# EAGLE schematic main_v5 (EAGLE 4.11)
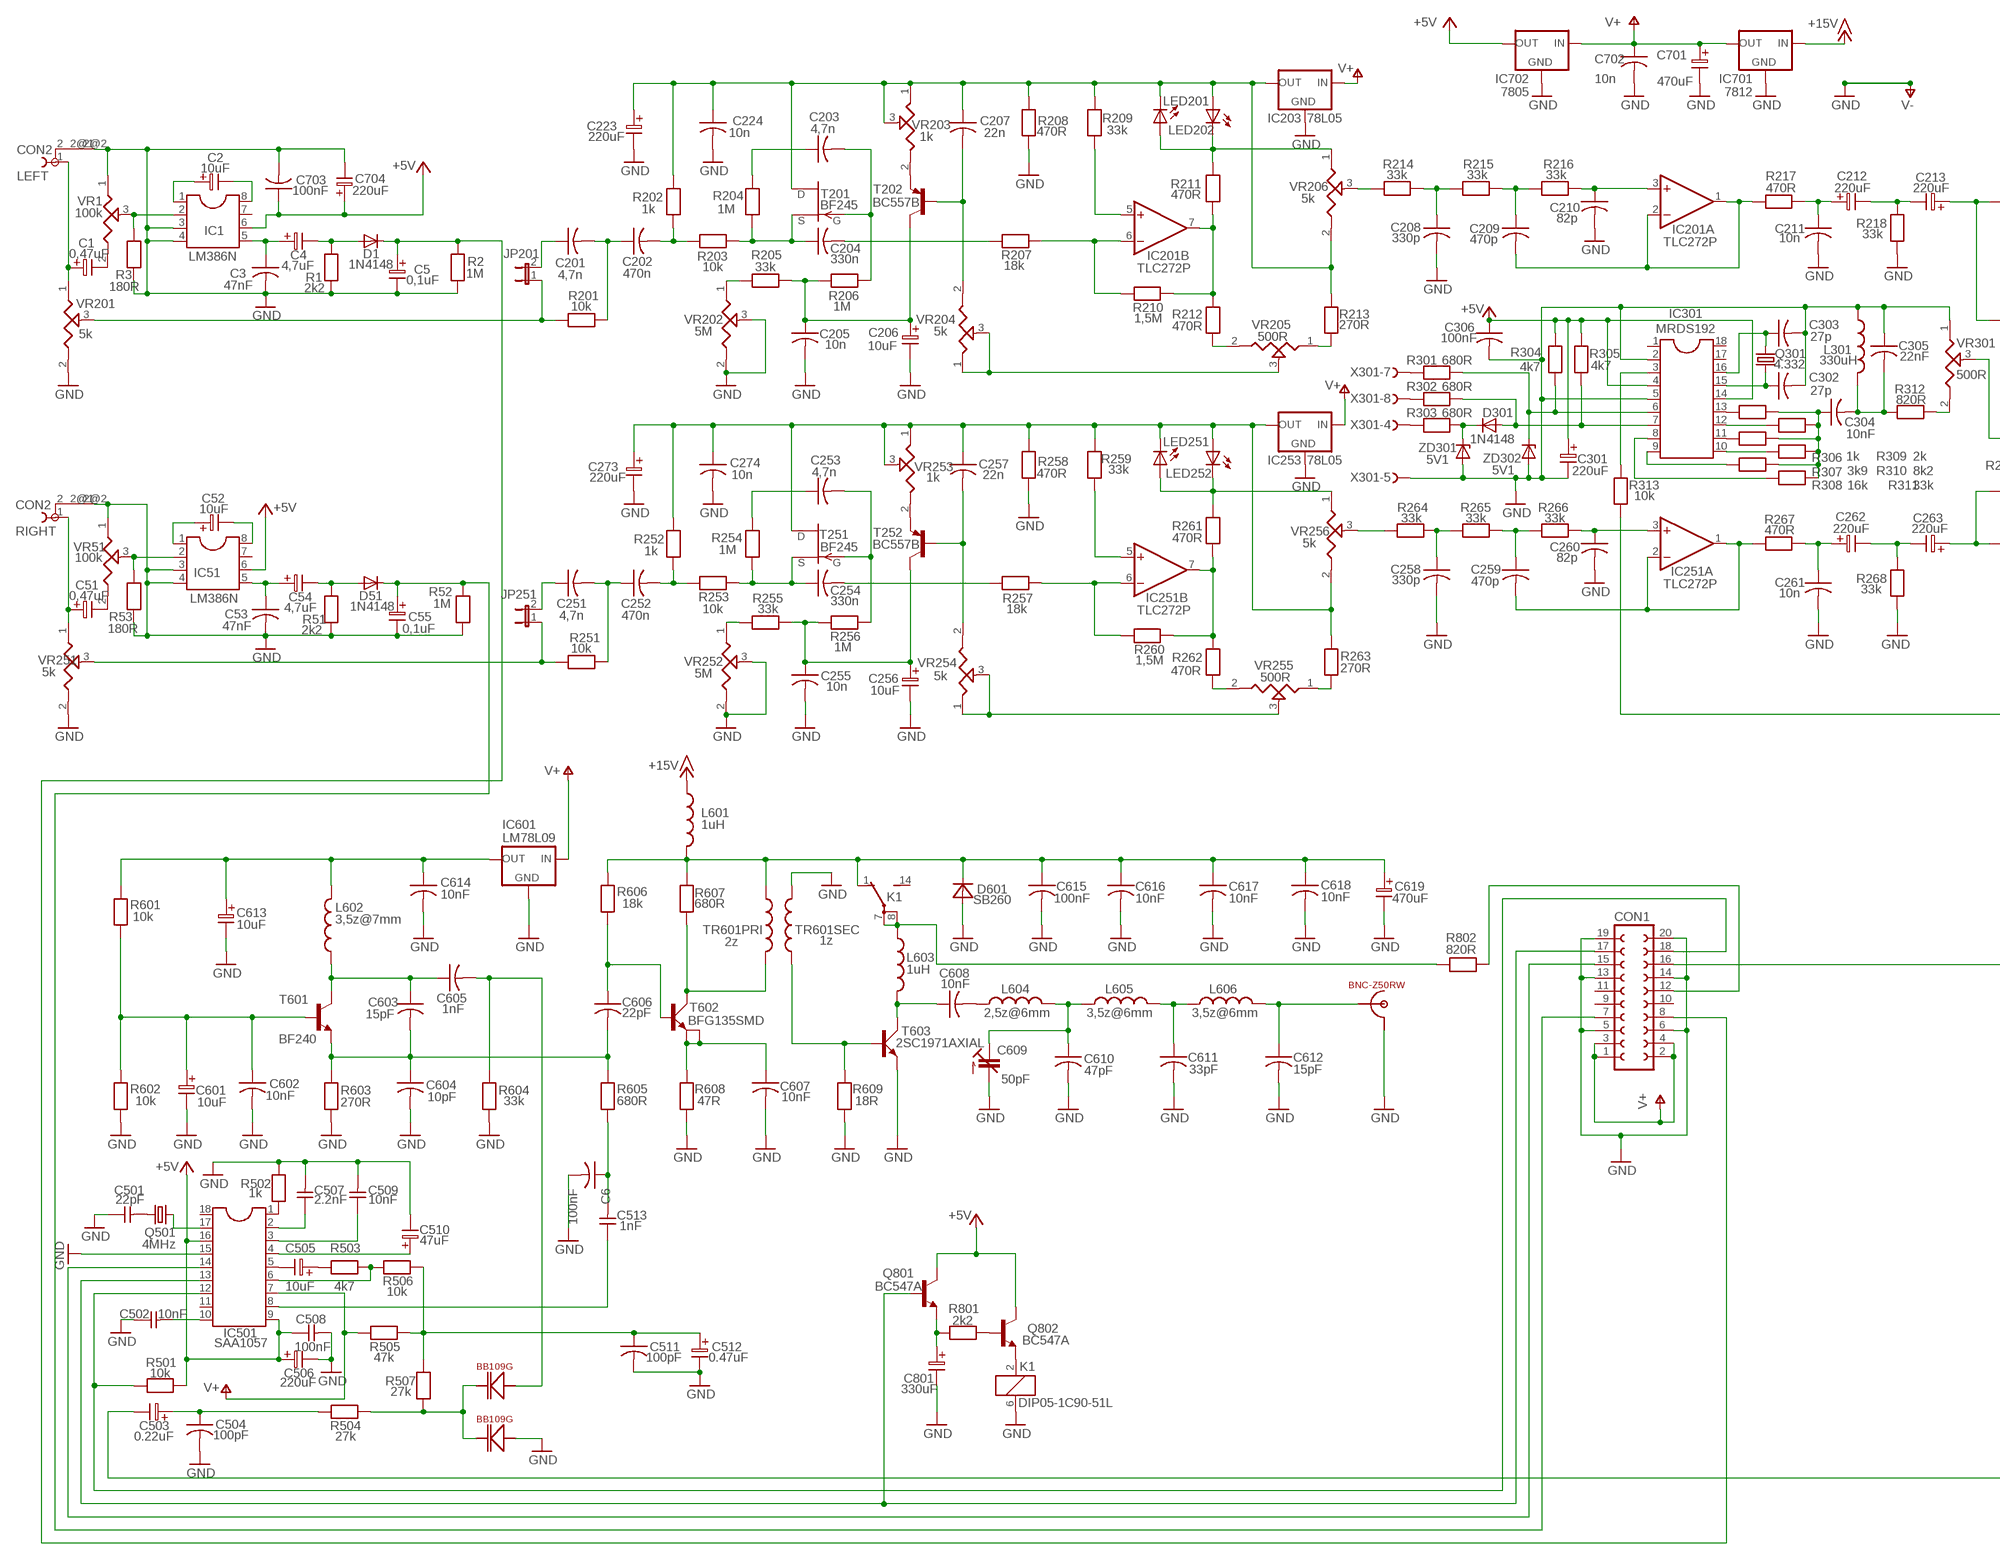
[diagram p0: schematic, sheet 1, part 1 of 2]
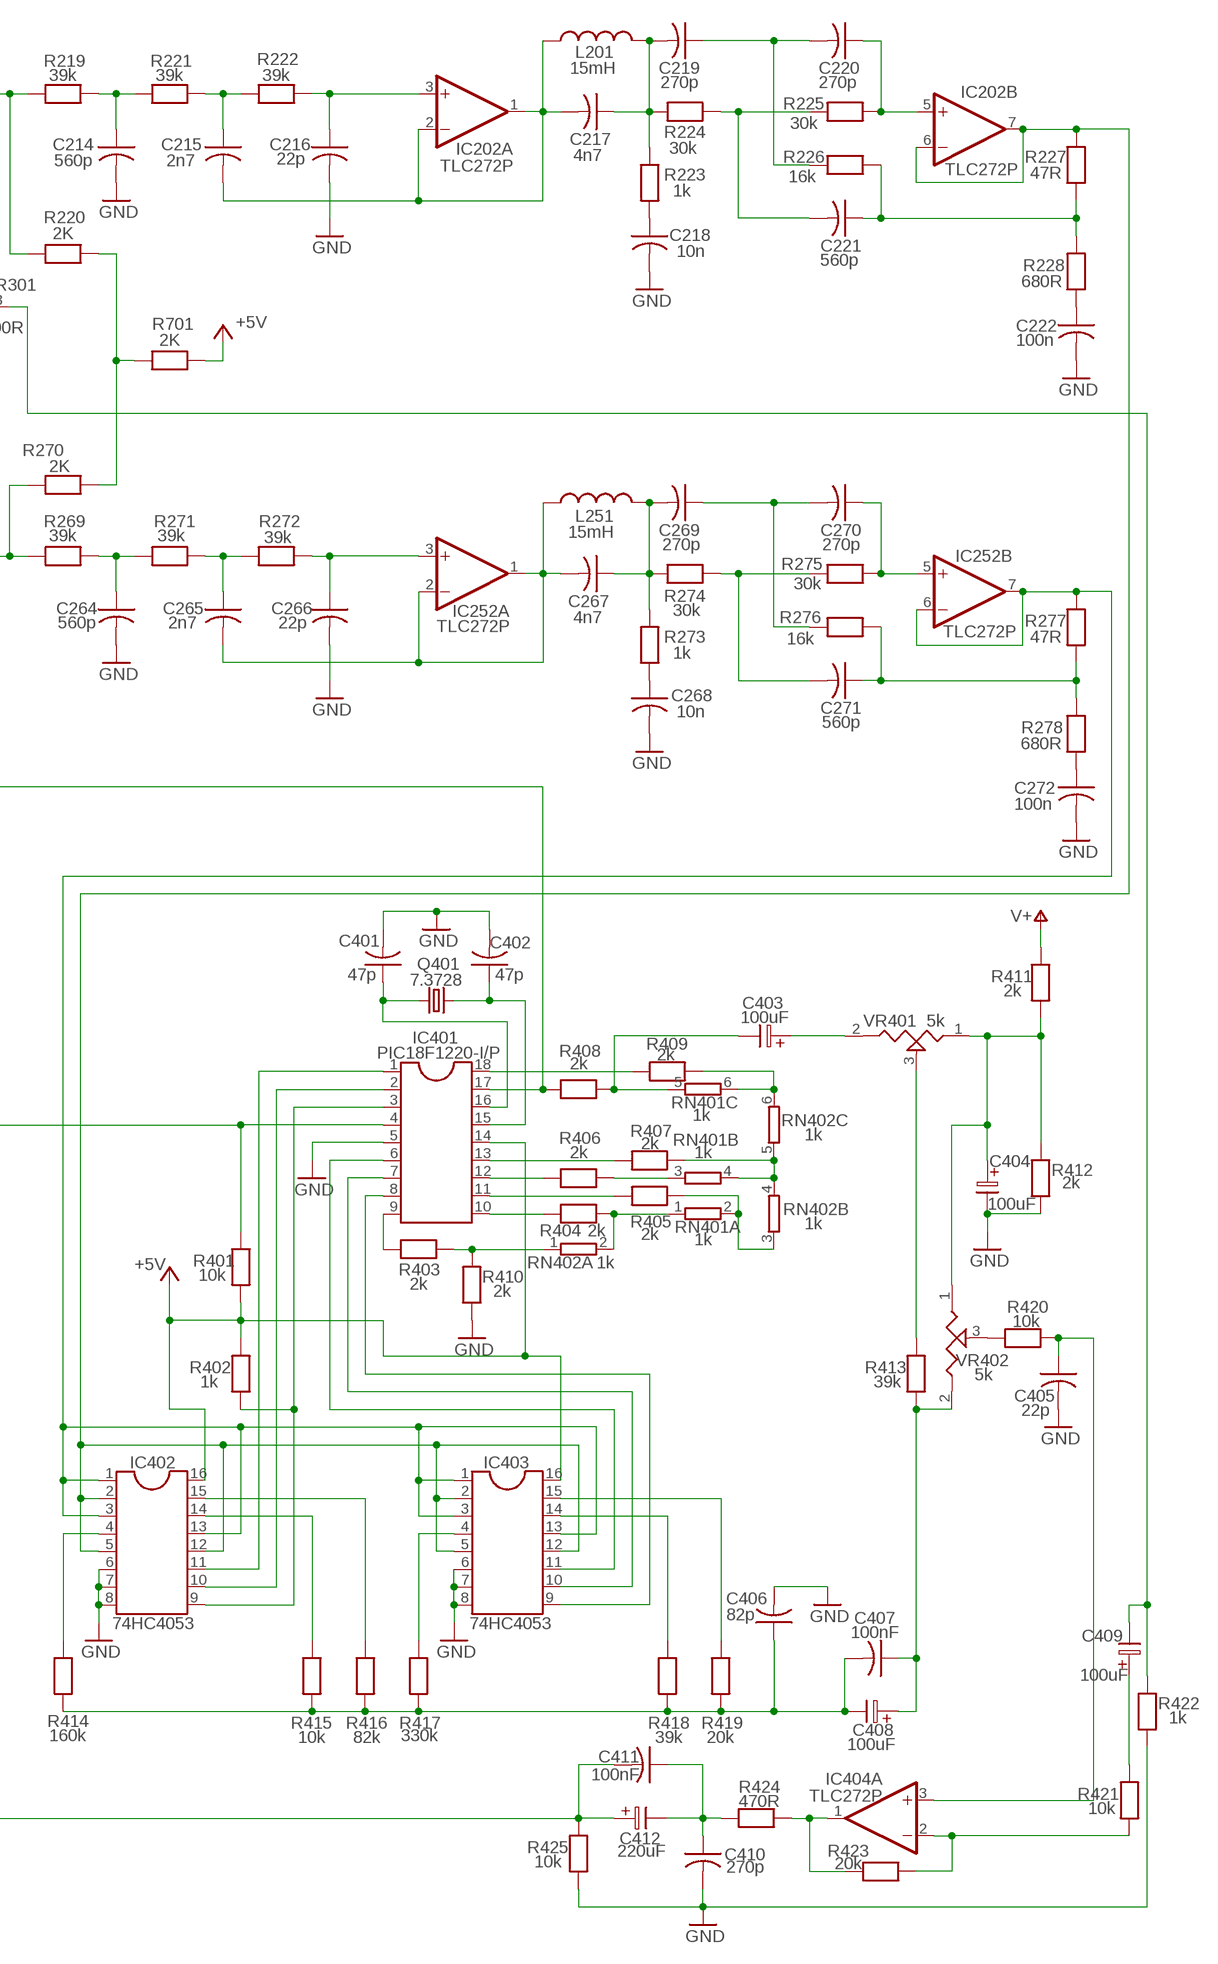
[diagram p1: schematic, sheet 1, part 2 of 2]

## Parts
C1  0,47uF  ELC-2,5  [ES-2,5]
C2  10uF  ELC-2,5  [ES-2,5]
C3  47nF  CAP-5  [C-5]
C4  4,7uF  ELC-2,5  [ES-2,5]
C5  0,1uF  ELC-2,5  [ES-2,5]
C6  100nF  CAP-5  [C-5]
C51  0,47uF  ELC-2,5  [ES-2,5]
C52  10uF  ELC-2,5  [ES-2,5]
C53  47nF  CAP-5  [C-5]
C54  4,7uF  ELC-2,5  [ES-2,5]
C55  0,1uF  ELC-2,5  [ES-2,5]
C201  4,7n  CAP-5  [C-5]
C202  470n  CAP-5  [C-5]
C203  4,7n  CAP-5  [C-5]
C204  330n  CAP-5  [C-5]
C205  10n  CAP-5  [C-5]
C206  10uF  ELC-2,5  [ES-2,5]
C207  22n  CAP-5  [C-5]
C208  330p  CAP-5  [C-5]
C209  470p  CAP-5  [C-5]
C210  82p  CAP-5  [C-5]
C211  10n  CAP-5  [C-5]
C212  220uF  ELC-5  [ES-5]
C213  220uF  ELC-2,5  [ES-2,5]
C214  560p  CAP-5  [C-5]
C215  2n7  CAP-5  [C-5]
C216  22p  CAP-5  [C-5]
C217  4n7  CAP-5  [C-5]
C218  10n  CAP-5  [C-5]
C219  270p  CAP-5  [C-5]
C220  270p  CAP-5  [C-5]
C221  560p  CAP-5  [C-5]
C222  100n  CAP-5  [C-5]
C223  220uF  ELC-2,5  [ES-2,5]
C224  10n  CAP-5  [C-5]
C251  4,7n  CAP-5  [C-5]
C252  470n  CAP-5  [C-5]
C253  4,7n  CAP-5  [C-5]
C254  330n  CAP-5  [C-5]
C255  10n  CAP-5  [C-5]
C256  10uF  ELC-2,5  [ES-2,5]
C257  22n  CAP-5  [C-5]
C258  330p  CAP-5  [C-5]
C259  470p  CAP-5  [C-5]
C260  82p  CAP-5  [C-5]
C261  10n  CAP-5  [C-5]
C262  220uF  ELC-5  [ES-5]
C263  220uF  ELC-2,5  [ES-2,5]
C264  560p  CAP-5  [C-5]
C265  2n7  CAP-5  [C-5]
C266  22p  CAP-5  [C-5]
C267  4n7  CAP-5  [C-5]
C268  10n  CAP-5  [C-5]
C269  270p  CAP-5  [C-5]
C270  270p  CAP-5  [C-5]
C271  560p  CAP-5  [C-5]
C272  100n  CAP-5  [C-5]
C273  220uF  ELC-2,5  [ES-2,5]
C274  10n  CAP-5  [C-5]
C301  220uF  ELC-5  [ES-5]
C302  27p  CAP-5  [C-5]
C303  27p  CAP-5  [C-5]
C304  10nF  CAP-5  [C-5]
C305  22nF  CAP-5  [C-5]
C306  100nF  CAP-5  [C-5]
C401  47p  CAP-5  [C-5]
C402  47p  CAP-5  [C-5]
C403  100uF  ELC-5  [ES-5]
C404  100uF  ELC-5  [ES-5]
C405  22p  CAP-5  [C-5]
C406  82p  CAP-5  [C-5]
C407  100nF  CAP-5  [C-5]
C408  100uF  ELC-5  [ES-5]
C409  100uF  ELC-5  [ES-5]
C410  270p  CAP-5  [C-5]
C411  100nF  CAP-5  [C-5]
C412  220uF  ELC-5  [ES-5]
C501  22pF  CAPNP-5  [C-5]
C502  10nF  CAPNP-5  [C-5]
C503  0.22uF  ELC-2,5  [ES-2,5]
C504  100pF  CAP-5  [C-5]
C505  10uF  ELC-2,5  [ES-2,5]
C506  220uF  ELC-5  [ES-5]
C507  2.2nF  CAPNP-5  [C-5]
C508  100nF  CAPNP-5  [C-5]
C509  10nF  CAPNP-5  [C-5]
C510  47uF  ELC-2,5  [ES-2,5]
C511  100pF  CAP-5  [C-5]
C512  0.47uF  ELC-2,5  [ES-2,5]
C513  1nF  CAPNP-5  [C-5]
C601  10uF  ELC-2,5  [ES-2,5]
C602  10nF  CAP-5  [C-5]
C603  15pF  CAP-5  [C-5]
C604  10pF  CAP-5  [C-5]
C605  1nF  CAP-5  [C-5]
C606  22pF  CAP-5  [C-5]
C607  10nF  CAP-5  [C-5]
C608  10nF  CAP-5  [C-5]
C609  50pF  C-TRIMM3008  [3008]
C610  47pF  CAP-5  [C-5]
C611  33pF  CAP-5  [C-5]
C612  15pF  CAP-5  [C-5]
C613  10uF  ELC-2,5  [ES-2,5]
C614  10nF  CAP-5  [C-5]
C615  100nF  CAP-5  [C-5]
C616  10nF  CAP-5  [C-5]
C617  10nF  CAP-5  [C-5]
C618  10nF  CAP-5  [C-5]
C619  470uF  ELC-5L  [ES-5L]
C701  470uF  ELC-5L  [ES-5L]
C702  10n  CAP-5  [C-5]
C703  100nF  CAP-5  [C-5]
C704  220uF  ELC-5  [ES-5]
C801  330uF  ELC-5  [ES-5]
CON1  FE10-2  [FE10-2]
D1  1N4148  [DO35-10]
D51  1N4148  [DO35-10]
D301  1N4148  [DO35-10]
D601  SB260  DIODE-7,5  [D-7,5]
IC1  LM386N  DIL8  [DIL08]
IC51  LM386N  DIL8  [DIL08]
IC201  TLC272P  [DIL08]
IC202  TLC272P  [DIL08]
IC203  78L05  78LXX  [78LXX]
IC251  TLC272P  [DIL08]
IC252  TLC272P  [DIL08]
IC253  78L05  78LXX  [78LXX]
IC301  MRDS192  DIL18  [DIL18]
IC401  PIC18F1220-I/P  DIL18  [DIL18]
IC402  74HC4053  DIL16  [DIL16]
IC403  74HC4053  DIL16  [DIL16]
IC404  TLC272P  [DIL08]
IC501  SAA1057  DIL18S  [SOCKED-18]
IC601  LM78L09  78LXX  [78LXX]
IC701  7812  78XXL  [78XXL]
IC702  7805  78XXL  [78XXL]
JP201  JP1E  [JP1]
JP251  JP1E  [JP1]
K1  DIP05-1C90-51L  RR1U  [RR1U]
L201  15mH  L-5  [L-5]
L251  15mH  L-5  [L-5]
L301  330uH  L-5  [L-5]
L601  1uH  L-12,5  [L-12,5]
L602  3,5z@7mm  L-10  [L-10]
L603  1uH  L-12,5  [L-12,5]
L604  2,5z@6mm  L-7,5  [L-7,5]
L605  3,5z@6mm  L-10  [L-10]
L606  3,5z@6mm  L-10  [L-10]
LED201  LED5MM  [LED5MM]
LED202  LED5MM  [LED5MM]
LED251  LED5MM  [LED5MM]
LED252  LED5MM  [LED5MM]
LEFT  CON2  TOBU3  [TOBU3]
Q301  4.332  CRYTALHC49S  [HC49/S]
Q401  7.3728  CRYTALHC49U-V  [HC49U-V]
Q501  4MHz  CRYTALHC49U-V  [HC49U-V]
Q801  BC547A  [TO92]
Q802  BC547A  [TO92]
R1  2k2  RESEU-7,5  [R-7,5]
R2  1M  RESEU-7,5  [R-7,5]
R3  180R  RESEU-7,5  [R-7,5]
R51  2k2  RESEU-7,5  [R-7,5]
R52  1M  RESEU-7,5  [R-7,5]
R53  180R  RESEU-7,5  [R-7,5]
R201  10k  RESEU-7,5  [R-7,5]
R202  1k  RESEU-7,5  [R-7,5]
R203  10k  RESEU-7,5  [R-7,5]
R204  1M  RESEU-7,5  [R-7,5]
R205  33k  RESEU-7,5  [R-7,5]
R206  1M  RESEU-7,5  [R-7,5]
R207  18k  RESEU-7,5  [R-7,5]
R208  470R  RESEU-7,5  [R-7,5]
R209  33k  RESEU-7,5  [R-7,5]
R210  1,5M  RESEU-7,5  [R-7,5]
R211  470R  RESEU-7,5  [R-7,5]
R212  470R  RESEU-7,5  [R-7,5]
R213  270R  RESEU-7,5  [R-7,5]
R214  33k  RESEU-7,5  [R-7,5]
R215  33k  RESEU-7,5  [R-7,5]
R216  33k  RESEU-7,5  [R-7,5]
R217  470R  RESEU-7,5  [R-7,5]
R218  33k  RESEU-7,5  [R-7,5]
R219  39k  RESEU-7,5  [R-7,5]
R220  2K  RESEU-7,5  [R-7,5]
R221  39k  RESEU-7,5  [R-7,5]
R222  39k  RESEU-7,5  [R-7,5]
R223  1k  RESEU-7,5  [R-7,5]
R224  30k  RESEU-7,5  [R-7,5]
R225  30k  RESEU-7,5  [R-7,5]
R226  16k  RESEU-7,5  [R-7,5]
R227  47R  RESEU-7,5  [R-7,5]
R228  680R  RESEU-7,5  [R-7,5]
R251  10k  RESEU-7,5  [R-7,5]
R252  1k  RESEU-7,5  [R-7,5]
R253  10k  RESEU-7,5  [R-7,5]
R254  1M  RESEU-7,5  [R-7,5]
R255  33k  RESEU-7,5  [R-7,5]
R256  1M  RESEU-7,5  [R-7,5]
R257  18k  RESEU-7,5  [R-7,5]
R258  470R  RESEU-7,5  [R-7,5]
R259  33k  RESEU-7,5  [R-7,5]
R260  1,5M  RESEU-7,5  [R-7,5]
R261  470R  RESEU-7,5  [R-7,5]
R262  470R  RESEU-7,5  [R-7,5]
R263  270R  RESEU-7,5  [R-7,5]
R264  33k  RESEU-7,5  [R-7,5]
R265  33k  RESEU-7,5  [R-7,5]
R266  33k  RESEU-7,5  [R-7,5]
R267  470R  RESEU-7,5  [R-7,5]
R268  33k  RESEU-7,5  [R-7,5]
R269  39k  RESEU-7,5  [R-7,5]
R270  2K  RESEU-7,5  [R-7,5]
R271  39k  RESEU-7,5  [R-7,5]
R272  39k  RESEU-7,5  [R-7,5]
R273  1k  RESEU-7,5  [R-7,5]
R274  30k  RESEU-7,5  [R-7,5]
R275  30k  RESEU-7,5  [R-7,5]
R276  16k  RESEU-7,5  [R-7,5]
R277  47R  RESEU-7,5  [R-7,5]
R278  680R  RESEU-7,5  [R-7,5]
R301  680R  RESEU-7,5  [R-7,5]
R302  680R  RESEU-7,5  [R-7,5]
R303  680R  RESEU-7,5  [R-7,5]
R304  4k7  RESEU-7,5  [R-7,5]
R305  4k7  RESEU-7,5  [R-7,5]
R306  1k  RESEU-7,5  [R-7,5]
R307  3k9  RESEU-7,5  [R-7,5]
R308  16k  RESEU-7,5  [R-7,5]
R309  2k  RESEU-7,5  [R-7,5]
R310  8k2  RESEU-7,5  [R-7,5]
R311  33k  RESEU-7,5  [R-7,5]
R312  820R  RESEU-7,5  [R-7,5]
R313  10k  RESEU-7,5  [R-7,5]
R401  10k  RESEU-7,5  [R-7,5]
R402  1k  RESEU-7,5  [R-7,5]
R403  2k  RESEU-7,5  [R-7,5]
R404  2k  RESEU-7,5  [R-7,5]
R405  2k  RESEU-7,5  [R-7,5]
R406  2k  RESEU-7,5  [R-7,5]
R407  2k  RESEU-7,5  [R-7,5]
R408  2k  RESEU-7,5  [R-7,5]
R409  2k  RESEU-7,5  [R-7,5]
R410  2k  RESEU-7,5  [R-7,5]
R411  2k  RESEU-7,5  [R-7,5]
R412  2k  RESEU-7,5  [R-7,5]
R413  39k  RESEU-7,5  [R-7,5]
R414  160k  RESEU-7,5  [R-7,5]
R415  10k  RESEU-7,5  [R-7,5]
R416  82k  RESEU-7,5  [R-7,5]
R417  330k  RESEU-7,5  [R-7,5]
R418  39k  RESEU-7,5  [R-7,5]
R419  20k  RESEU-7,5  [R-7,5]
R420  10k  RESEU-7,5  [R-7,5]
R421  10k  RESEU-7,5  [R-7,5]
R422  1k  RESEU-7,5  [R-7,5]
R423  20k  RESEU-7,5  [R-7,5]
R424  470R  RESEU-7,5  [R-7,5]
R425  10k  RESEU-7,5  [R-7,5]
R501  10k  RESEU-7,5  [R-7,5]
R502  1k  RESEU-7,5  [R-7,5]
R503  4k7  RESEU-7,5  [R-7,5]
R504  27k  RESEU-7,5  [R-7,5]
R505  47k  RESEU-7,5  [R-7,5]
R506  10k  RESEU-7,5  [R-7,5]
R507  27k  RESEU-7,5  [R-7,5]
R601  10k  RESEU-7,5  [R-7,5]
R602  10k  RESEU-7,5  [R-7,5]
R603  270R  RESEU-7,5  [R-7,5]
R604  33k  RESEU-7,5  [R-7,5]
R605  680R  RESEU-7,5  [R-7,5]
R606  18k  RESEU-7,5  [R-7,5]
R607  680R  RESEU-7,5  [R-7,5]
R608  47R  RESEU-7,5  [R-7,5]
R609  18R  RESEU-7,5  [R-7,5]
R701  2K  RESEU-7,5  [R-7,5]
R801  2k2  RESEU-7,5  [R-7,5]
R802  820R  RESEU-7,5  [R-7,5]
RIGHT  CON2  TOBU3  [TOBU3]
RN401  1k  E3R  [SIL6]
RN402  1k  E3R  [SIL6]
T201  BF245  [TO92]
T202  BC557B  BC557B-PNP-TO92-EBC  [TO92-EBC]
T251  BF245  [TO92]
T252  BC557B  [TO92-EBC]
T601  BF240  BF374-NPN-TO92-CEB  [TO92-CEB]
T602  BFG135SMD  [SOT223]
T603  2SC1971AXIAL  [TO220AH]
TR601PRI  2z  L-7,5  [L-7,5]
TR601SEC  1z  L-7,5  [L-7,5]
U$6  BNC-Z50RW  [BNC-Z50RW]
U$7  BB109G  [BB1X]
U$8  BB109G  [BB1X]
VR1  100k  POTUS-L  [PT-10]
VR51  100k  POTUS-L  [PT-10]
VR201  5k  POTUS-L  [PT-10]
VR202  5M  POTUS-L  [PT-10]
VR203  1k  POTUS-L  [PT-10]
VR204  5k  POTUS-L  [PT-10]
VR205  500R  POTUS-L  [PT-10]
VR206  5k  POTUS-L  [PT-10]
VR251  5k  POTUS-L  [PT-10]
VR252  5M  POTUS-L  [PT-10]
VR253  1k  POTUS-L  [PT-10]
VR254  5k  POTUS-L  [PT-10]
VR255  500R  POTUS-L  [PT-10]
VR256  5k  POTUS-L  [PT-10]
VR301  500R  POTUS-L  [PT-10]
VR401  5k  POTUS-L  [PT-10]
VR402  5k  POTUS-L  [PT-10]
X301  F09HPS  [F09HP]
ZD301  5V1  BZV10  [DO34Z7]
ZD302  5V1  BZV10  [DO34Z7]

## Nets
+5V: C301.1 C306.1 C506.1 C508.1 C703.1 C704.1 IC1.6 IC51.6 IC301.4 IC301.14 IC401.14 IC402.16 IC403.16 IC501.9 IC501.16 IC702.OUT Q801.3(C) Q802.3(C) R304.2 R305.2 R401.1 R402.2 R501.2 R701.2
+15V: IC701.IN L601.1
GND: C3.2 C5.2 C6.2 C53.2 C55.2 C205.2 C206.2 C208.2 C210.2 C211.2 C214.2 C216.2 C218.2 C222.2 C223.2 C224.2 C255.2 C256.2 C258.2 C260.2 C261.2 C264.2 C266.2 C268.2 C272.2 C273.2 C274.2 C301.2 C302.2 C303.2 C305.1 C306.2 C401.2 C402.2 C404.2 C405.2 C406.2 C410.2 C501.1 C502.1 C504.2 C506.2 C507.2 C508.2 C509.2 C510.2 C511.2 C512.2 C601.2 C602.2 C604.2 C607.2 C609.-(A) C610.2 C611.2 C612.2 C613.2 C614.2 C615.2 C616.2 C617.2 C618.2 C619.2 C701.2 C702.2 C703.2 C704.2 C801.2 CON1.5 CON1.6 CON1.13 CON1.14 CON1.19 CON1.20 D601.1(A) IC1.3 IC1.4 IC51.3 IC51.4 IC203.GND IC253.GND IC301.2 IC301.5 IC401.5 IC402.6 IC402.7 IC402.8 IC403.6 IC403.7 IC403.8 IC501.15 IC601.GND IC701.GND IC702.GND K1.6 L301.1 LEFT.2@2 R1.1 R2.1 R3.1 R51.1 R52.1 R53.1 R208.1 R218.1 R258.1 R268.1 R410.1 R412.1 R422.2 R425.1 R502.2 R602.1 R603.1 R604.1 R608.1 R609.1 RIGHT.2@2 T603.2(E) TR601SEC.2 U$6.P$4 U$8.P$2 VR1.1 VR51.1 VR201.2 VR202.2 VR202.3 VR251.2 VR252.2 VR252.3 VR301.1 X301.5(-5:F) ZD301.A ZD302.A ; supply symbol labelled V-
IC402: IC252.6(B:-IN) IC252.7(B:OUT) IC402.1 IC402.3 IC402.13 IC403.1 IC403.3 IC403.13 R277.2
N$1: C405.1 IC404.3(A:+IN) R420.2
N$2: C201.1 JP201.2
N$3: C201.2 C202.1 R201.2
N$4: C202.2 R202.1 R203.1
N$5: C204.1 R203.2 R204.1 T201.2(S)
N$6: IC1.2 R3.2 VR1.3
N$7: T202.E VR203.2
N$8: R205.1 VR202.1
N$9: C203.1 R204.2
N$10: C203.2 R206.1 T201.3(G)
N$11: C205.1 C206.1 R205.2 R206.2 T202.C
N$12: C204.2 R207.1
N$13: C207.2 T202.B VR204.2
N$14: VR204.1 VR204.3 VR205.3
N$15: IC201.5(B:+IN) R209.1
N$16: IC201.7(B:OUT) R210.2 R211.1 R212.2
N$17: LED201.A LED202.K(C) R211.2 VR206.1
N$18: R214.1 VR206.3
N$19: R212.1 VR205.2
N$20: IC201.6(B:-IN) R207.2 R210.1
N$21: R213.1 VR205.1
N$22: C212.2 C213.2 R218.2
N$23: C208.1 R214.2 R215.1
N$24: C209.1 R215.2 R216.1
N$25: C210.1 IC201.3(A:+IN) R216.2
N$26: C211.1 C212.1 R217.2
N$27: C252.2 R252.1 R253.1
N$28: C209.2 IC201.1(A:OUT) IC201.2(A:-IN) R217.1
N$29: C262.2 C263.2 R268.2
N$30: C251.2 C252.1 R251.2
N$31: C251.1 JP251.2
N$32: JP251.1 R251.1 VR251.3
N$33: T252.E VR253.2
N$34: C254.1 R253.2 R254.1 T251.2(S)
N$35: C253.1 R254.2
N$36: C253.2 R256.2 T251.3(G)
N$37: C255.1 C256.1 R255.2 R256.1 T252.C
N$38: R255.1 VR252.1
N$39: C51.2 VR51.2
N$40: C257.2 T252.B VR254.2
N$41: C254.2 R257.1
N$42: IC251.5(B:+IN) R259.1
N$43: IC251.6(B:-IN) R257.2 R260.1
N$44: LED251.A LED252.K(C) R261.2 VR256.1
N$45: IC251.7(B:OUT) R260.2 R261.1 R262.2
N$46: R264.1 VR256.3
N$47: C258.1 R264.2 R265.1
N$48: C259.1 R265.2 R266.1
N$49: R262.1 VR255.2
N$50: VR254.1 VR254.3 VR255.3
N$51: R263.1 VR255.1
N$52: C51.1 RIGHT.1 VR251.1
N$53: C260.1 IC251.3(A:+IN) R266.2
N$54: C259.2 IC251.1(A:OUT) IC251.2(A:-IN) R267.1
N$55: C261.1 C262.1 R267.2
N$56: C257.1 C273.1 C274.1 IC253.OUT LED251.K(C) LED252.A R252.2 R258.2 R259.2 R263.2 T251.1(D) VR253.1 VR253.3 VR256.2
N$57: JP201.1 R201.1 VR201.3
N$58: IC51.2 R53.2 VR51.3
N$59: C1.1 LEFT.1 VR201.1
N$60: C52.1 IC51.1
N$61: C52.2 IC51.8
N$62: C54.2 D51.A R51.2
N$63: C55.1 CON1.7 D51.C R52.2
N$64: C1.2 VR1.2
N$65: C613.1 C614.1 IC601.OUT L602.2 R601.2
N$66: C601.1 C602.1 R601.1 R602.2 T601.B
N$67: C603.1 C605.1 L602.1 T601.C
N$68: C603.2 C604.1 C606.2 R603.2 R605.2 T601.E
N$69: C605.2 R604.2 U$7.P$2
N$70: C606.1 R606.1 T602.2(B)
N$71: R607.1 T602.4(C) TR601PRI.2
N$72: C6.1 C513.2 R605.1
N$73: C607.1 R608.2 T602.1(E1) T602.3(E2)
N$74: R609.2 T603.1(B) TR601SEC.1
N$75: C5.1 CON1.8 D1.C R2.2
N$76: C608.1 L603.2 T603.3(C)
N$77: C608.2 L604.1
N$78: R301.1 X301.7(-7:F)
N$79: C611.1 L605.2 L606.1
N$80: C612.1 L606.2 U$6.P$3
N$81: R303.1 X301.4(-4:F)
N$82: C609.+(E) C610.1 L604.2 L605.1
N$83: C503.1 C504.1 R504.1
N$84: C615.1 C616.1 C617.1 C618.1 C619.1 D601.2(K) K1.1(2:O) L601.2 R606.2 R607.2 TR601PRI.1
N$85: C501.2 Q501.1
N$86: IC501.17 Q501.2
N$87: CON1.15 IC501.14
N$88: CON1.17 IC501.13 Q801.2(B)
N$89: CON1.18 IC501.12 R501.1
N$90: C3.1 C4.1 IC1.5
N$91: C4.2 D1.A R1.2
N$92: R302.1 X301.8(-8:F)
N$93: C502.2 IC501.10
N$94: C411.2 C412.1 C503.2 R425.2
N$95: IC301.6 R301.2 R304.1 ZD302.C
N$96: C2.2 IC1.8
N$97: D301.A IC301.7 R302.2 R305.1
N$98: IC501.1 R502.1
N$99: C2.1 IC1.1
N$100: C207.1 C223.1 C224.1 IC203.OUT LED201.K(C) LED202.A R202.2 R208.2 R209.2 R213.2 T201.1(D) VR203.1 VR203.3 VR206.2
N$101: D301.C R303.2 ZD301.C
N$102: C303.1 IC301.15 Q301.1
N$103: C302.1 IC301.16 Q301.2
N$104: IC301.13 R306.1
N$105: IC301.11 R307.1
N$106: R220.2 R270.2 R701.1
N$107: IC301.12 R309.1
N$108: IC301.10 R310.1
N$109: IC301.9 R308.1
N$110: IC301.8 R311.1
N$111: C304.1 R306.2 R307.2 R308.2 R309.2 R310.2 R311.2
N$112: C304.2 C305.2 L301.2 R312.1
N$113: R312.2 VR301.2
N$114: C507.1 IC501.2
N$115: C509.1 IC501.3
N$116: C510.1 IC501.4
N$117: C505.2 IC501.5
N$118: C505.1 R503.1
N$119: IC501.6 R503.2 R506.2
N$120: R504.2 R507.1 U$7.P$1 U$8.P$1
N$121: IC401.3 IC402.9 R402.1
N$122: C513.1 IC501.8
N$123: CON1.16 IC401.4 R401.2
N$124: R407.2 RN401.4 RN402.4 RN402.5
N$125: C217.1 C219.2 L201.2 R223.2 R224.1
N$126: C267.1 C269.2 L251.2 R273.2 R274.1
N$127: IC402.4 R414.2
N$128: IC402.14 R415.2
N$129: IC402.15 R416.2
N$130: IC401.6 IC403.11
N$131: C801.1 Q801.1(E) R801.1
N$132: IC202.6(B:-IN) IC202.7(B:OUT) IC402.2 IC402.5 IC402.12 IC403.2 IC403.5 IC403.12 R227.2
N$133: IC401.7 IC403.10
N$134: IC403.4 R417.2
N$135: IC403.14 R418.2
N$136: IC403.15 R419.2
N$137: C265.2 C267.2 IC252.1(A:OUT) IC252.2(A:-IN) L251.1
N$139: C406.1 C407.2 C408.2 R414.1 R415.1 R416.1 R417.1 R418.1 R419.1
N$140: C263.1 R269.1 R270.1
N$141: C264.1 R269.2 R271.1
N$142: C213.1 R219.1 R220.1
N$143: C214.1 R219.2 R221.1
N$144: C215.1 R221.2 R222.1
N$145: C216.1 IC202.3(A:+IN) R222.2
N$146: C265.1 R271.2 R272.1
N$147: C266.1 IC252.3(A:+IN) R272.2
N$148: C268.1 R273.1
N$149: C218.1 R223.1
N$150: C215.2 C217.2 IC202.1(A:OUT) IC202.2(A:-IN) L201.1
N$151: C53.1 C54.1 IC51.5
N$152: IC401.8 IC403.9
N$153: C269.1 C270.2 R276.1
N$154: C271.2 R274.2 R275.1
N$155: C270.1 IC252.5(B:+IN) R275.2
N$156: C271.1 R276.2 R277.1 R278.2
N$157: IC401.9 R403.2
N$158: R403.1 R410.2 RN402.1
N$159: C272.1 R278.1
N$161: C511.1 C512.1 R505.2 R506.1 R507.2
N$162: C222.1 R228.1
N$163: C221.2 R224.2 R225.1
N$164: C219.1 C220.2 R226.1
N$165: C220.1 IC202.5(B:+IN) R225.2
N$166: C221.1 R226.2 R227.1 R228.2
N$167: C401.1 IC401.16 Q401.1
N$168: IC401.1 IC402.11
N$169: IC401.2 IC402.10
N$170: Q802.2(B) R801.2
N$171: C402.1 IC401.15 Q401.2
N$172: C403.1 VR401.2
N$173: IC401.17 R313.1 R408.1
N$174: IC401.18 R409.1
N$175: IC301.3 R313.2
N$176: IC401.10 R404.1
N$177: IC401.11 R405.1
N$178: IC401.12 R406.1
N$179: IC401.13 R407.1
N$180: R404.2 RN401.1 RN402.2
N$181: R405.2 RN401.2 RN402.3
N$182: R406.2 RN401.3
N$183: K1.2 Q802.1(E)
N$184: C403.2 R408.2 RN401.5
N$185: R409.2 RN401.6 RN402.6
N$186: C404.1 R411.1 R412.2 VR401.1 VR402.1
N$187: IC404.1(A:OUT) R423.1 R424.2
N$188: R413.2 VR401.3
N$189: IC404.2(A:-IN) R421.1 R423.2
N$190: C407.1 C408.1 R413.1 VR402.2
N$191: R420.1 VR402.3
N$193: CON1.12 R802.1
N$194: C410.1 C411.1 C412.2 R424.1
N$195: K1.7(2:P) K1.8(2:P) L603.1 R802.2
N$197: C409.1 R421.2
N$198: C409.2 R422.1 VR301.3
V+: C701.1 C702.1 CON1.1 CON1.2 CON1.3 CON1.4 IC203.IN IC253.IN IC501.7 IC601.IN IC701.OUT IC702.IN R411.2 R505.1
Unconnected: CON1.9 CON1.10 CON1.11 IC1.7 IC51.7 IC301.1 IC301.17 IC301.18 IC404.5(B:+IN) IC404.6(B:-IN) IC404.7(B:OUT) IC501.11 IC501.18 K1.14(2:S) LEFT.2 LEFT.2@1 RIGHT.2 RIGHT.2@1 X301.1(-1:F) X301.2(-2:F) X301.3(-3:F) X301.6(-6:F) X301.9(-9:F) X301.G1(-G:G1) X301.G2(-G:G2)

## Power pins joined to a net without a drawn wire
GND: IC201.4(P:V-) IC202.4(P:V-) IC251.4(P:V-) IC252.4(P:V-) IC404.4(P:V-)
V+: IC201.8(P:V+) IC202.8(P:V+) IC251.8(P:V+) IC252.8(P:V+) IC404.8(P:V+)

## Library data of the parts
C1 C2 C4 C5 C51 C52 C54 C55 C206 C213 C223 C256 C263 C273 C503 C505 C510 C512 C601 C613 = discrete:ELC-2,5
C3 C6 C53 C201-C205 C207-C211 C214-C222 C224 C251-C255 C257-C261 C264-C272 C274 C302-C306 C401 C402 C405-C407 C410 C411 C504 C511 C602-C608 C610-C612 C614-C618 C702 C703 = discrete:CAP-5
C212 C262 C301 C403 C404 C408 C409 C412 C506 C704 C801 = discrete:ELC-5
C501 C502 C507-C509 C513 = discrete:CAPNP-5
C609 = c-trimm:C-TRIMM: Trimm capacitor
C619 C701 = discrete:ELC-5L
CON1 = con-lsta:FE10-2: FEMALE HEADER
D1 D51 D301 = diode:1N4148: DIODE
D601 = discrete:DIODE-7,5
IC1 IC51 = ic-package:DIL8: Dual In Line
IC201 IC202 IC251 IC252 IC404 = linear:TLC272: OP AMP
IC203 IC253 IC601 = v-reg:78LXX: VOLTAGE REGULATOR
IC301 IC401 IC501 = ic-package:DIL18: Dual In Line
IC402 IC403 = ic-package:DIL16: Dual In Line
IC701 IC702 = v-reg:78XXL: VOLTAGE REGULATOR
JP201 JP251 = jumper:JP1E: JUMPER
K1 = relay:RR1U: RELAY reed, polarity, 1 x switch with shield
L201 L251 L301 = discrete:L-5
L601 L603 = discrete:L-12,5
L602 L605 L606 = discrete:L-10
L604 TR601PRI TR601SEC = discrete:L-7,5
LED201 LED202 LED251 LED252 = led:LED: LED
LEFT RIGHT = con-hirschmann:TOBU3: Female Cinch CONNECTOR
Q301 Q401 Q501 = crystal:CRYTAL: CRYSTAL
Q801 Q802 = transistor-npn:BC547*: NPN Transistor
R1-R3 R51-R53 R201-R228 R251-R278 R301-R313 R401-R425 R501-R507 R601-R609 R701 R801 R802 = discrete:RESEU-7,5
RN401 RN402 = resistor-sil:E3R: SIL RESISTOR
T201 T251 = transistor-fet:BF245: N-Channel Junction FET
T202 = transistor:*-PNP-: PNP Transistror
T252 = transistor-pnp:BC557*: PNP Transistror
T601 = transistor-special:*-NPN-: NPN Transistror
T602 = _user-semicon:BFG135
T603 = _user-semicon:2SC1971: NPN TRANSISTOR
U$6 = _user-semicon:BNC-Z50RW
U$7 U$8 = _user-semicon:BB109G
VR1 VR51 VR201-VR206 VR251-VR256 VR301 VR401 VR402 = discrete:POTUS-L
X301 = con-subd:F09HPS: SUB-D
ZD301 ZD302 = diode:BZV10: Z DIODE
